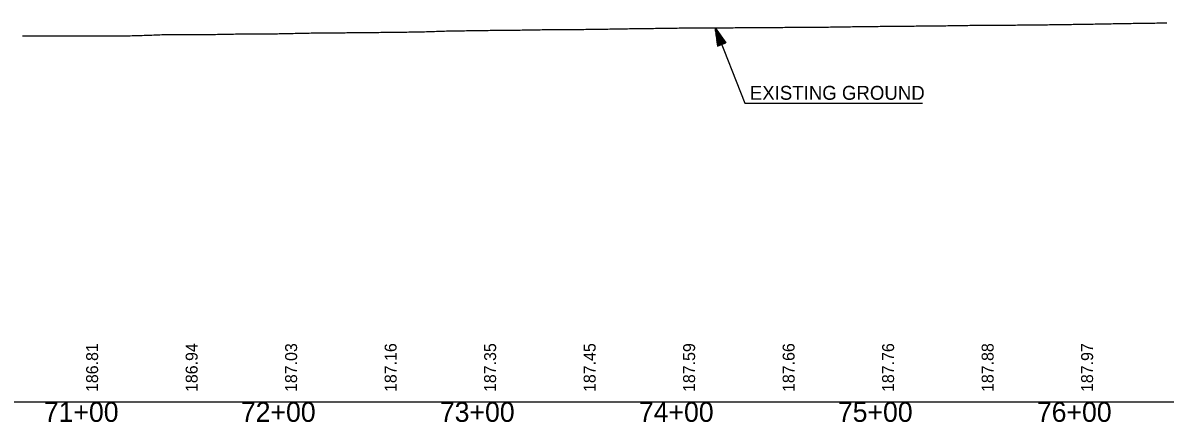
# Model space of a CAD drawing. Extents: x 69 to 2003113, y 512 to 837401.
# Drawn here: x 1894448 to 1895022, y 820540 to 820741 of the extents above; entities that cross this region are included whole.
import ezdxf

# ---------------------------------------------------------------- set-up
doc = ezdxf.new("R2010")
doc.units = 0
for name, color, linetype in [('BR_BORDER LINES', 7, 'Continuous'), ('BR_CONCRETE', 7, 'Continuous'), ('BR_TEXT', 7, 'Continuous'), ('RD_PD_ALT1_TrvlWay', 7, 'Continuous'), ('RD_SHT_ID', 7, 'Continuous')]:
    doc.layers.add(name, color=color, linetype=linetype)

msp = doc.modelspace()

# ---------------------------------------------------------------- linework, layer by layer
at = {"layer": 'BR_BORDER LINES'}
msp.add_line((1889077.53, 820550.13), (1895477.53, 820550.13), dxfattribs=at)
at = {"layer": 'BR_TEXT'}
for points in [[(1894704.6, 820737.2), (1894705.6, 820737.22), (1894706.6, 820737.23), (1894707.6, 820737.24), (1894708.6, 820737.26), (1894709.6, 820737.27), (1894710.6, 820737.27), (1894711.6, 820737.26), (1894712.6, 820737.26), (1894713.6, 820737.27), (1894714.6, 820737.28), (1894715.6, 820737.28), (1894716.6, 820737.29), (1894717.6, 820737.3), (1894718.6, 820737.3), (1894719.6, 820737.31), (1894720.6, 820737.32), (1894721.6, 820737.33), (1894722.6, 820737.34), (1894723.6, 820737.35), (1894724.6, 820737.36), (1894725.6, 820737.37), (1894726.6, 820737.39), (1894727.6, 820737.4), (1894728.6, 820737.41), (1894729.6, 820737.42), (1894730.6, 820737.44), (1894731.6, 820737.45), (1894732.6, 820737.46), (1894733.6, 820737.48), (1894734.6, 820737.49), (1894735.6, 820737.51), (1894736.6, 820737.53), (1894737.6, 820737.54), (1894738.6, 820737.55), (1894739.6, 820737.57), (1894740.6, 820737.58), (1894741.6, 820737.59), (1894742.6, 820737.6), (1894743.6, 820737.62), (1894744.6, 820737.63), (1894745.6, 820737.64), (1894746.6, 820737.66), (1894747.6, 820737.68), (1894748.6, 820737.7), (1894749.6, 820737.72), (1894750.6, 820737.73), (1894751.6, 820737.75), (1894752.6, 820737.76), (1894753.6, 820737.78), (1894754.6, 820737.79), (1894755.6, 820737.8), (1894756.6, 820737.82), (1894757.6, 820737.83), (1894758.6, 820737.85), (1894759.6, 820737.86), (1894760.6, 820737.87), (1894761.6, 820737.88), (1894762.6, 820737.89), (1894763.6, 820737.91), (1894764.6, 820737.92), (1894765.6, 820737.93), (1894766.6, 820737.95), (1894767.6, 820737.96), (1894768.6, 820737.97), (1894769.6, 820737.98), (1894770.6, 820738), (1894771.6, 820738.01), (1894772.6, 820738.03), (1894773.6, 820738.04), (1894774.6, 820738.05), (1894775.6, 820738.07), (1894776.6, 820738.08), (1894777.6, 820738.1), (1894778.6, 820738.11), (1894779.6, 820738.13), (1894780.6, 820738.14), (1894781.6, 820738.15), (1894782.6, 820738.17), (1894783.6, 820738.18), (1894784.6, 820738.2), (1894785.6, 820738.21), (1894786.6, 820738.21), (1894787.6, 820738.22), (1894788.6, 820738.22), (1894789.6, 820738.22), (1894790.6, 820738.22), (1894791.6, 820738.23), (1894792.6, 820738.23), (1894793.6, 820738.23), (1894794.6, 820738.23), (1894795.6, 820738.24), (1894796.6, 820738.24), (1894797.6, 820738.24), (1894798.6, 820738.24), (1894799.6, 820738.24), (1894800.6, 820738.25), (1894801.6, 820738.25), (1894802.6, 820738.25), (1894803.6, 820738.26), (1894804.6, 820738.26)], [(1894804.6, 820738.26), (1894805.6, 820738.27), (1894806.6, 820738.27), (1894807.6, 820738.27), (1894808.6, 820738.28), (1894809.6, 820738.29), (1894810.6, 820738.3), (1894811.6, 820738.31), (1894812.6, 820738.33), (1894813.6, 820738.34), (1894814.6, 820738.35), (1894815.6, 820738.36), (1894816.6, 820738.37), (1894817.6, 820738.38), (1894818.6, 820738.39), (1894819.6, 820738.4), (1894820.6, 820738.4), (1894821.6, 820738.4), (1894822.6, 820738.41), (1894823.6, 820738.41), (1894824.6, 820738.41), (1894825.6, 820738.41), (1894826.6, 820738.42), (1894827.6, 820738.42), (1894828.6, 820738.42), (1894829.6, 820738.42), (1894830.6, 820738.43), (1894831.6, 820738.43), (1894832.6, 820738.43), (1894833.6, 820738.43), (1894834.6, 820738.44), (1894835.6, 820738.44), (1894836.6, 820738.44), (1894837.6, 820738.44), (1894838.6, 820738.44), (1894839.6, 820738.44), (1894840.6, 820738.44), (1894841.6, 820738.45), (1894842.6, 820738.45), (1894843.6, 820738.45), (1894844.6, 820738.45), (1894845.6, 820738.46), (1894846.6, 820738.48), (1894847.6, 820738.49), (1894848.6, 820738.51), (1894849.6, 820738.53), (1894850.6, 820738.54), (1894851.6, 820738.56), (1894852.6, 820738.58), (1894853.6, 820738.6), (1894854.6, 820738.61), (1894855.6, 820738.63), (1894856.6, 820738.65), (1894857.6, 820738.67), (1894858.6, 820738.68), (1894859.6, 820738.7), (1894860.6, 820738.71), (1894861.6, 820738.73), (1894862.6, 820738.74), (1894863.6, 820738.75), (1894864.6, 820738.77), (1894865.6, 820738.78), (1894866.6, 820738.8), (1894867.6, 820738.81), (1894868.6, 820738.82), (1894869.6, 820738.83), (1894870.6, 820738.84), (1894871.6, 820738.85), (1894872.6, 820738.87), (1894873.6, 820738.88), (1894874.6, 820738.89), (1894875.6, 820738.9), (1894876.6, 820738.91), (1894877.6, 820738.92), (1894878.6, 820738.94), (1894879.6, 820738.95), (1894880.6, 820738.96), (1894881.6, 820738.97), (1894882.6, 820738.98), (1894883.6, 820738.99), (1894884.6, 820738.99), (1894885.6, 820739), (1894886.6, 820739.01), (1894887.6, 820739.02), (1894888.6, 820739.03), (1894889.6, 820739.03), (1894890.6, 820739.04), (1894891.6, 820739.05), (1894892.6, 820739.06), (1894893.6, 820739.06), (1894894.6, 820739.08), (1894895.6, 820739.09), (1894896.6, 820739.1), (1894897.6, 820739.1), (1894898.6, 820739.11), (1894899.6, 820739.12), (1894900.6, 820739.13), (1894901.6, 820739.14), (1894902.6, 820739.15), (1894903.6, 820739.16), (1894904.6, 820739.16)], [(1894904.6, 820739.16), (1894905.6, 820739.17), (1894906.6, 820739.19), (1894907.6, 820739.2), (1894908.6, 820739.21), (1894909.6, 820739.23), (1894910.6, 820739.24), (1894911.6, 820739.26), (1894912.6, 820739.27), (1894913.6, 820739.29), (1894914.6, 820739.3), (1894915.6, 820739.32), (1894916.6, 820739.33), (1894917.6, 820739.34), (1894918.6, 820739.36), (1894919.6, 820739.38), (1894920.6, 820739.39), (1894921.6, 820739.41), (1894922.6, 820739.43), (1894923.6, 820739.45), (1894924.6, 820739.47), (1894925.6, 820739.49), (1894926.6, 820739.5), (1894927.6, 820739.52), (1894928.6, 820739.54), (1894929.6, 820739.56), (1894930.6, 820739.56), (1894931.6, 820739.56), (1894932.6, 820739.56), (1894933.6, 820739.56), (1894934.6, 820739.56), (1894935.6, 820739.56), (1894936.6, 820739.56), (1894937.6, 820739.56), (1894938.6, 820739.56), (1894939.6, 820739.56), (1894940.6, 820739.56), (1894941.6, 820739.56), (1894942.6, 820739.56), (1894943.6, 820739.57), (1894944.6, 820739.58), (1894945.6, 820739.59), (1894946.6, 820739.6), (1894947.6, 820739.61), (1894948.6, 820739.62), (1894949.6, 820739.63), (1894950.6, 820739.64), (1894951.6, 820739.64), (1894952.6, 820739.65), (1894953.6, 820739.66), (1894954.6, 820739.67), (1894955.6, 820739.69), (1894956.6, 820739.7), (1894957.6, 820739.71), (1894958.6, 820739.72), (1894959.6, 820739.73), (1894960.6, 820739.74), (1894961.6, 820739.75), (1894962.6, 820739.76), (1894963.6, 820739.77), (1894964.6, 820739.78), (1894965.6, 820739.79), (1894966.6, 820739.8), (1894967.6, 820739.82), (1894968.6, 820739.83), (1894969.6, 820739.85), (1894970.6, 820739.86), (1894971.6, 820739.88), (1894972.6, 820739.89), (1894973.6, 820739.91), (1894974.6, 820739.92), (1894975.6, 820739.94), (1894976.6, 820739.96), (1894977.6, 820739.97), (1894978.6, 820739.99), (1894979.6, 820740.01), (1894980.6, 820740.02), (1894981.6, 820740.04), (1894982.6, 820740.06), (1894983.6, 820740.07), (1894984.6, 820740.09), (1894985.6, 820740.1), (1894986.6, 820740.12), (1894987.6, 820740.14), (1894988.6, 820740.15), (1894989.6, 820740.17), (1894990.6, 820740.19), (1894991.6, 820740.21), (1894992.6, 820740.22), (1894993.6, 820740.24), (1894994.6, 820740.26), (1894995.6, 820740.28), (1894996.6, 820740.29), (1894997.6, 820740.31), (1894998.6, 820740.33), (1894999.6, 820740.34), (1895000.6, 820740.36), (1895001.6, 820740.38), (1895002.6, 820740.39), (1895003.6, 820740.41), (1895004.6, 820740.43)], [(1895004.6, 820740.43), (1895005.6, 820740.44), (1895006.6, 820740.46), (1895007.6, 820740.47), (1895008.6, 820740.49), (1895009.6, 820740.5), (1895010.6, 820740.52), (1895011.6, 820740.53), (1895012.6, 820740.54), (1895013.6, 820740.55), (1895014.6, 820740.57), (1895015.6, 820740.58), (1895016.6, 820740.6), (1895017.6, 820740.61), (1895018.6, 820740.63), (1895019.6, 820740.64), (1895020.6, 820740.66), (1895021.6, 820740.67), (1895022.6, 820740.69)], [(1894447.6, 820734.12), (1894448.6, 820734.13), (1894449.6, 820734.14), (1894450.6, 820734.14), (1894451.6, 820734.15), (1894452.6, 820734.15), (1894453.6, 820734.16), (1894454.6, 820734.16), (1894455.6, 820734.16), (1894456.6, 820734.16), (1894457.6, 820734.16), (1894458.6, 820734.16), (1894459.6, 820734.17), (1894460.6, 820734.17), (1894461.6, 820734.17), (1894462.6, 820734.17), (1894463.6, 820734.17), (1894464.6, 820734.17), (1894465.6, 820734.18), (1894466.6, 820734.18), (1894467.6, 820734.18), (1894468.6, 820734.18), (1894469.6, 820734.19), (1894470.6, 820734.2), (1894471.6, 820734.21), (1894472.6, 820734.22), (1894473.6, 820734.21), (1894474.6, 820734.2), (1894475.6, 820734.19), (1894476.6, 820734.19), (1894477.6, 820734.18), (1894478.6, 820734.17), (1894479.6, 820734.16), (1894480.6, 820734.16), (1894481.6, 820734.15), (1894482.6, 820734.14), (1894483.6, 820734.13), (1894484.6, 820734.13), (1894485.6, 820734.12), (1894486.6, 820734.11), (1894487.6, 820734.11), (1894488.6, 820734.11), (1894489.6, 820734.12), (1894490.6, 820734.13), (1894491.6, 820734.14), (1894492.6, 820734.15), (1894493.6, 820734.16), (1894494.6, 820734.17), (1894495.6, 820734.18), (1894496.6, 820734.19), (1894497.6, 820734.2), (1894498.6, 820734.21), (1894499.6, 820734.22), (1894500.6, 820734.23), (1894501.6, 820734.24), (1894502.6, 820734.25), (1894503.6, 820734.26), (1894504.6, 820734.27)], [(1894504.6, 820734.27), (1894505.6, 820734.29), (1894506.6, 820734.33), (1894507.6, 820734.37), (1894508.6, 820734.41), (1894509.6, 820734.45), (1894510.6, 820734.49), (1894511.6, 820734.53), (1894512.6, 820734.57), (1894513.6, 820734.61), (1894514.6, 820734.65), (1894515.6, 820734.69), (1894516.6, 820734.73), (1894517.6, 820734.76), (1894518.6, 820734.77), (1894519.6, 820734.78), (1894520.6, 820734.79), (1894521.6, 820734.79), (1894522.6, 820734.8), (1894523.6, 820734.81), (1894524.6, 820734.81), (1894525.6, 820734.82), (1894526.6, 820734.82), (1894527.6, 820734.83), (1894528.6, 820734.84), (1894529.6, 820734.84), (1894530.6, 820734.85), (1894531.6, 820734.85), (1894532.6, 820734.85), (1894533.6, 820734.85), (1894534.6, 820734.85), (1894535.6, 820734.85), (1894536.6, 820734.86), (1894537.6, 820734.86), (1894538.6, 820734.86), (1894539.6, 820734.86), (1894540.6, 820734.86), (1894541.6, 820734.86), (1894542.6, 820734.86), (1894543.6, 820734.88), (1894544.6, 820734.9), (1894545.6, 820734.92), (1894546.6, 820734.93), (1894547.6, 820734.95), (1894548.6, 820734.97), (1894549.6, 820734.99), (1894550.6, 820735.01), (1894551.6, 820735.02), (1894552.6, 820735.04), (1894553.6, 820735.06), (1894554.6, 820735.08), (1894555.6, 820735.08), (1894556.6, 820735.09), (1894557.6, 820735.09), (1894558.6, 820735.1), (1894559.6, 820735.1), (1894560.6, 820735.11), (1894561.6, 820735.11), (1894562.6, 820735.12), (1894563.6, 820735.13), (1894564.6, 820735.13), (1894565.6, 820735.14), (1894566.6, 820735.15), (1894567.6, 820735.15), (1894568.6, 820735.16), (1894569.6, 820735.17), (1894570.6, 820735.18), (1894571.6, 820735.19), (1894572.6, 820735.2), (1894573.6, 820735.21), (1894574.6, 820735.22), (1894575.6, 820735.23), (1894576.6, 820735.25), (1894577.6, 820735.27), (1894578.6, 820735.29), (1894579.6, 820735.31), (1894580.6, 820735.33), (1894581.6, 820735.36), (1894582.6, 820735.38), (1894583.6, 820735.4), (1894584.6, 820735.42), (1894585.6, 820735.44), (1894586.6, 820735.46), (1894587.6, 820735.49), (1894588.6, 820735.51), (1894589.6, 820735.53), (1894590.6, 820735.55), (1894591.6, 820735.57), (1894592.6, 820735.59), (1894593.6, 820735.61), (1894594.6, 820735.63), (1894595.6, 820735.65), (1894596.6, 820735.67), (1894597.6, 820735.68), (1894598.6, 820735.68), (1894599.6, 820735.68), (1894600.6, 820735.68), (1894601.6, 820735.68), (1894602.6, 820735.68), (1894603.6, 820735.68), (1894604.6, 820735.68)], [(1894604.6, 820735.68), (1894605.6, 820735.69), (1894606.6, 820735.7), (1894607.6, 820735.72), (1894608.6, 820735.73), (1894609.6, 820735.74), (1894610.6, 820735.75), (1894611.6, 820735.77), (1894612.6, 820735.78), (1894613.6, 820735.79), (1894614.6, 820735.8), (1894615.6, 820735.82), (1894616.6, 820735.83), (1894617.6, 820735.84), (1894618.6, 820735.85), (1894619.6, 820735.86), (1894620.6, 820735.86), (1894621.6, 820735.87), (1894622.6, 820735.88), (1894623.6, 820735.89), (1894624.6, 820735.89), (1894625.6, 820735.9), (1894626.6, 820735.91), (1894627.6, 820735.92), (1894628.6, 820735.93), (1894629.6, 820735.95), (1894630.6, 820735.96), (1894631.6, 820735.97), (1894632.6, 820735.98), (1894633.6, 820735.99), (1894634.6, 820736.01), (1894635.6, 820736.02), (1894636.6, 820736.03), (1894637.6, 820736.04), (1894638.6, 820736.05), (1894639.6, 820736.06), (1894640.6, 820736.07), (1894641.6, 820736.09), (1894642.6, 820736.1), (1894643.6, 820736.11), (1894644.6, 820736.12), (1894645.6, 820736.13), (1894646.6, 820736.15), (1894647.6, 820736.18), (1894648.6, 820736.21), (1894649.6, 820736.24), (1894650.6, 820736.28), (1894651.6, 820736.31), (1894652.6, 820736.34), (1894653.6, 820736.37), (1894654.6, 820736.41), (1894655.6, 820736.44), (1894656.6, 820736.48), (1894657.6, 820736.51), (1894658.6, 820736.54), (1894659.6, 820736.58), (1894660.6, 820736.59), (1894661.6, 820736.61), (1894662.6, 820736.63), (1894663.6, 820736.64), (1894664.6, 820736.66), (1894665.6, 820736.68), (1894666.6, 820736.69), (1894667.6, 820736.71), (1894668.6, 820736.73), (1894669.6, 820736.75), (1894670.6, 820736.76), (1894671.6, 820736.78), (1894672.6, 820736.8), (1894673.6, 820736.81), (1894674.6, 820736.83), (1894675.6, 820736.84), (1894676.6, 820736.85), (1894677.6, 820736.87), (1894678.6, 820736.88), (1894679.6, 820736.89), (1894680.6, 820736.91), (1894681.6, 820736.92), (1894682.6, 820736.93), (1894683.6, 820736.95), (1894684.6, 820736.96), (1894685.6, 820736.96), (1894686.6, 820736.97), (1894687.6, 820736.98), (1894688.6, 820736.99), (1894689.6, 820737), (1894690.6, 820737.01), (1894691.6, 820737.02), (1894692.6, 820737.02), (1894693.6, 820737.03), (1894694.6, 820737.04), (1894695.6, 820737.05), (1894696.6, 820737.06), (1894697.6, 820737.08), (1894698.6, 820737.1), (1894699.6, 820737.13), (1894700.6, 820737.14), (1894701.6, 820737.16), (1894702.6, 820737.17), (1894703.6, 820737.19), (1894704.6, 820737.2)]]:
    msp.add_lwpolyline(points, dxfattribs=at)
at = {"layer": 'RD_PD_ALT1_TrvlWay'}
for p, q in [((1894795.6, 820738.24), (1894810.56, 820700.28)), ((1894798.9, 820729.86), (1894795.6, 820738.24)), ((1894795.6, 820738.24), (1894801, 820730.69)), ((1894795.6, 820738.24), (1894796.81, 820729.04)), ((1894796.81, 820729.04), (1894801, 820730.69)), ((1894810.56, 820700.28), (1894899.75, 820700.28))]:
    msp.add_line(p, q, dxfattribs=at)
for points in [[(1894798.8, 820729.94), (1894795.73, 820737.74), (1894798.77, 820729.87), (1894795.8, 820737.35), (1894798.67, 820729.87), (1894795.83, 820737.08), (1894798.56, 820729.85), (1894795.86, 820736.75), (1894798.48, 820729.8), (1894795.93, 820736.26), (1894798.36, 820729.73), (1894796.02, 820735.73), (1894798.25, 820729.73), (1894796.07, 820735.33), (1894798.17, 820729.67), (1894796.13, 820734.88), (1894798.06, 820729.69), (1894796.19, 820734.48), (1894798, 820729.59), (1894796.23, 820734.13), (1894797.86, 820729.58), (1894796.28, 820733.64), (1894797.77, 820729.52), (1894796.4, 820733.04), (1894797.67, 820729.46), (1894796.4, 820732.62), (1894797.57, 820729.42), (1894796.49, 820732), (1894797.45, 820729.41), (1894796.59, 820731.49), (1894797.35, 820729.31), (1894796.64, 820731.05), (1894797.25, 820729.31), (1894796.68, 820730.65), (1894797.16, 820729.22), (1894796.75, 820730.16), (1894797.05, 820729.25), (1894796.83, 820729.61), (1894796.93, 820729.25)], [(1894795.88, 820737.72), (1894798.92, 820729.99), (1894796.04, 820737.46), (1894799.03, 820730.03), (1894796.19, 820737.22), (1894799.11, 820730.03), (1894796.37, 820737.01), (1894799.17, 820730.07), (1894796.58, 820736.75), (1894799.26, 820730.09), (1894796.76, 820736.5), (1894799.33, 820730.11), (1894796.97, 820736.21), (1894799.43, 820730.13), (1894797.22, 820735.84), (1894799.54, 820730.2), (1894797.42, 820735.52), (1894799.62, 820730.19), (1894797.65, 820735.2), (1894799.7, 820730.24), (1894797.89, 820734.89), (1894799.79, 820730.27), (1894798.13, 820734.54), (1894799.84, 820730.35), (1894798.45, 820734.09), (1894799.94, 820730.35), (1894798.68, 820733.8), (1894800.02, 820730.35), (1894798.97, 820733.41), (1894800.1, 820730.41), (1894799.21, 820733.01), (1894800.19, 820730.47), (1894799.44, 820732.7), (1894800.28, 820730.57), (1894799.69, 820732.42), (1894800.35, 820730.59), (1894799.97, 820731.95), (1894800.49, 820730.57), (1894800.16, 820731.68), (1894800.63, 820730.63), (1894800.34, 820731.51), (1894800.74, 820730.77), (1894800.86, 820730.72), (1894800.7, 820730.75)]]:
    msp.add_lwpolyline(points, dxfattribs=at)

# ---------------------------------------------------------------- texts
at = {"layer": 'BR_CONCRETE'}
for s, p in [('186.81', (1894485.53, 820555.13)), ('186.94', (1894535.53, 820555.13)), ('187.03', (1894585.53, 820555.13)), ('187.16', (1894635.53, 820555.13)), ('187.35', (1894685.53, 820555.13)), ('187.45', (1894735.53, 820555.13)), ('187.59', (1894785.53, 820555.13)), ('187.66', (1894835.53, 820555.13)), ('187.76', (1894885.53, 820555.13)), ('187.88', (1894935.53, 820555.13)), ('187.97', (1894985.53, 820555.13))]:
    msp.add_text(s, height=6, rotation=90, dxfattribs=at).set_placement(p)
at = {"layer": 'RD_PD_ALT1_TrvlWay'}
msp.add_text('EXISTING GROUND', height=7, dxfattribs=at).set_placement((1894813.03, 820702.01))
at = {"layer": 'RD_SHT_ID'}
for s, p in [('71+00', (1894458.25, 820540.13)), ('72+00', (1894557.29, 820540.13)), ('73+00', (1894657.29, 820540.13)), ('74+00', (1894757.29, 820540.13)), ('75+00', (1894857.29, 820540.13)), ('76+00', (1894957.29, 820540.13))]:
    msp.add_text(s, height=10, dxfattribs=at).set_placement(p)

doc.saveas('drawing.dxf')
